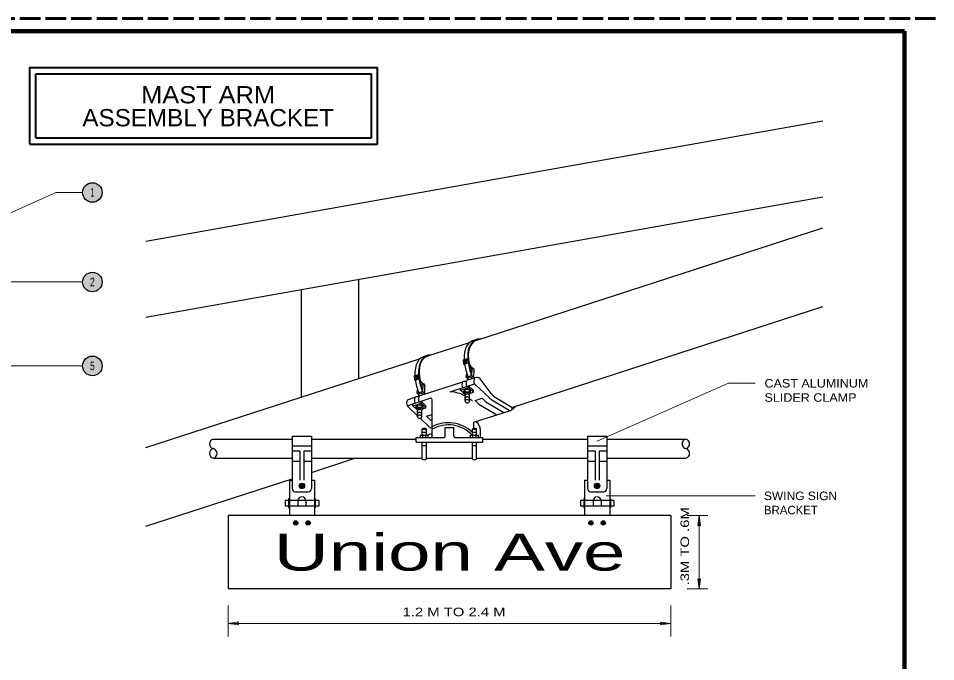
# Model space of a CAD drawing. Extents: x 312583 to 312853, y 144376 to 144586.
# Drawn here: x 312771.1 to 312851.8, y 144529.7 to 144586.2 of the extents above; entities that cross this region are included whole.
import ezdxf
from ezdxf.enums import TextEntityAlignment as Align

# ---------------------------------------------------------------- set-up
doc = ezdxf.new("R2010")
doc.units = 0
doc.header["$LTSCALE"] = 0.3
doc.linetypes.add('LONG_DASHED', pattern=[7.5, 6, -1.5])
for name, color, linetype, lineweight in [('1', 7, 'Continuous', 25), ('2', 7, 'Continuous', 13), ('63', 7, 'LONG_DASHED', 60)]:
    doc.layers.add(name, color=color, linetype=linetype, lineweight=lineweight)

msp = doc.modelspace()

# ---------------------------------------------------------------- hatches: boundary and pattern name
at = {"layer": '1'}
h = msp.add_hatch(color=256, dxfattribs=at)
edge = h.paths.add_edge_path()
edge.add_ellipse((312810.348, 144556.0743), major_axis=(-0.0325, -0.118), ratio=0.5966872, start_angle=0, end_angle=360)
h = msp.add_hatch(color=256, dxfattribs=at)
edge = h.paths.add_edge_path()
edge.add_ellipse((312806.0191, 144554.6706), major_axis=(-0.0325, -0.118), ratio=0.5966872, start_angle=0, end_angle=360)
for points in [[(312796.2425, 144545.1199, 1), (312795.7605, 144545.1199, 1)], [(312796.1712, 144545.1199, 1), (312795.8318, 144545.1199, 1)], [(312822.212, 144545.1199, 1), (312821.73, 144545.1199, 1)], [(312822.1407, 144545.1199, 1), (312821.8013, 144545.1199, 1)], [(312795.6532, 144541.8642, 1), (312795.2709, 144541.8642, 1)], [(312796.732, 144541.8642, 1), (312796.3497, 144541.8642, 1)], [(312821.6226, 144541.8642, 1), (312821.2403, 144541.8642, 1)], [(312822.7015, 144541.8642, 1), (312822.3192, 144541.8642, 1)]]:
    msp.add_hatch(color=256, dxfattribs=at).paths.add_polyline_path(points)
at = {"layer": '2'}
for points in [[(312778.4291, 144570.918, 1), (312776.7088, 144570.918, 1)], [(312778.4291, 144563.0427, 1), (312776.7088, 144563.0427, 1)], [(312778.4291, 144555.6707, 1), (312776.7088, 144555.6707, 1)]]:
    msp.add_hatch(color=256, dxfattribs=at).paths.add_polyline_path(points)

# ---------------------------------------------------------------- linework, layer by layer
at = {"layer": '1', "lineweight": 158}
msp.add_line((312849, 144423.1446), (312849, 144585.0846), dxfattribs=at)
at = {"layer": '1'}
for p, q in [((312782.2774, 144566.6365), (312841.8212, 144577.2025)), ((312782.2774, 144559.9598), (312841.8212, 144570.5258)), ((312811.3085, 144557.904), (312841.8212, 144567.8125)), ((312801.0203, 144554.5703), (312801.0203, 144563.2842)), ((312795.9641, 144552.9312), (312795.9641, 144562.386)), ((312814.4662, 144552.0144), (312841.8212, 144560.8951)), ((312807.0765, 144556.5427), (312810.7529, 144557.7373)), ((312782.2774, 144548.4955), (312806.4375, 144556.3297)), ((312810.2158, 144556.2001), (312810.5862, 144556.3205)), ((312810.688, 144556.2186), (312810.5862, 144556.3205)), ((312810.6325, 144555.9408), (312810.5862, 144556.3205)), ((312810.2528, 144555.8204), (312810.2158, 144556.2001)), ((312810.2528, 144555.8204), (312810.6325, 144555.9408)), ((312810.3269, 144555.7463), (312810.2528, 144555.8204)), ((312810.3176, 144555.9593), (312810.3917, 144555.9315)), ((312810.3824, 144556.1908), (312810.4473, 144556.1723)), ((312810.7343, 144555.8389), (312810.6325, 144555.9408)), ((312810.7343, 144555.8389), (312810.688, 144556.2186)), ((312810.6973, 144555.8297), (312810.7343, 144555.8389)), ((312805.8912, 144554.7925), (312806.2616, 144554.9129)), ((312805.9282, 144554.4129), (312805.8912, 144554.7925)), ((312806.0579, 144554.7925), (312806.1227, 144554.7647)), ((312806.2986, 144554.5332), (312806.2616, 144554.9129)), ((312806.3635, 144554.8203), (312806.2616, 144554.9129)), ((312806.4098, 144554.4314), (312806.3635, 144554.8203)), ((312810.4565, 144554.6814), (312810.5121, 144555.0055)), ((312810.4565, 144554.6814), (312810.9195, 144554.8296)), ((312810.4565, 144554.6814), (312810.6139, 144554.5055)), ((312810.7992, 144555.4037), (312811.0214, 144555.4778)), ((312810.9195, 144554.8296), (312811.0214, 144555.4778)), ((312810.9195, 144554.8296), (312811.1325, 144554.5888)), ((312811.1325, 144554.5888), (312811.1418, 144555.4037)), ((312805.9282, 144554.4129), (312806.2986, 144554.5332)), ((312805.993, 144554.348), (312805.9282, 144554.4129)), ((312805.993, 144554.5518), (312806.0579, 144554.5332)), ((312806.4098, 144554.4314), (312806.2986, 144554.5332)), ((312806.3264, 144553.0423), (312810.1602, 144554.2832)), ((312806.3727, 144554.4221), (312806.4098, 144554.4314)), ((312806.4746, 144553.9961), (312806.6968, 144554.0702)), ((312806.595, 144553.422), (312806.6968, 144554.0702)), ((312806.808, 144553.1905), (312806.808, 144553.9961)), ((312809.0397, 144553.3942), (312811.1881, 144554.0795)), ((312810.5213, 144554.4036), (312811.1973, 144554.6166)), ((312810.6139, 144554.4221), (312810.6139, 144554.5703)), ((312811.0955, 144553.5146), (312810.6695, 144553.9128)), ((312812.4938, 144552.8479), (312811.1881, 144554.0795)), ((312812.642, 144553.2461), (312811.6789, 144554.5332)), ((312806.132, 144553.2738), (312806.1783, 144553.5979)), ((312806.132, 144553.2738), (312806.595, 144553.422)), ((312806.132, 144553.2738), (312806.2801, 144553.0979)), ((312806.2801, 144552.9219), (312806.2801, 144553.1535)), ((312806.595, 144553.422), (312806.808, 144553.1905)), ((312810.3547, 144553.6165), (312810.2435, 144553.4683)), ((312810.3547, 144553.1812), (312810.2435, 144553.2553)), ((312810.3547, 144553.1535), (312810.2713, 144553.2368)), ((312810.3547, 144553.6165), (312810.7343, 144553.6165)), ((312810.3547, 144553.4035), (312810.3547, 144553.6165)), ((312810.3547, 144553.4035), (312810.7343, 144553.4035)), ((312810.3547, 144552.5608), (312810.3547, 144553.1812)), ((312811.0955, 144553.3572), (312810.6695, 144553.7646)), ((312810.7343, 144553.4035), (312810.7343, 144553.6165)), ((312810.7343, 144553.6165), (312810.8455, 144553.4683)), ((312810.7343, 144553.4035), (312810.8455, 144553.2553)), ((312810.8455, 144553.2553), (312810.7343, 144553.1812)), ((312810.7343, 144552.5608), (312810.7343, 144553.1812)), ((312810.8455, 144553.2553), (312810.8455, 144553.4683)), ((312805.2707, 144552.1626), (312805.7708, 144552.3293)), ((312805.2893, 144552.6997), (312805.9745, 144552.9219)), ((312805.7708, 144552.3293), (312806.4931, 144552.5701)), ((312805.7708, 144552.1719), (312805.7708, 144552.3293)), ((312806.4931, 144552.5701), (312807.2802, 144552.8201)), ((312806.9098, 144552.1533), (312806.4931, 144552.5701)), ((312806.9098, 144551.9959), (312806.4931, 144552.4034)), ((312807.4469, 144549.3845), (312807.4469, 144552.6997)), ((312811.5678, 144552.32), (312813.1513, 144551.3662)), ((312812.1789, 144552.5145), (312811.8548, 144552.8201)), ((312812.1789, 144552.5145), (312813.7717, 144551.5699)), ((312812.7068, 144552.6812), (312814.244, 144551.7644)), ((312812.9938, 144552.9127), (312814.4199, 144552.07)), ((312806.169, 144551.2921), (312805.3726, 144552.0422)), ((312806.0579, 144551.9033), (312805.7708, 144552.1719)), ((312806.169, 144552.2552), (312806.0579, 144552.1163)), ((312806.169, 144551.82), (312806.0579, 144551.9033)), ((312806.169, 144551.8014), (312806.0857, 144551.8848)), ((312806.169, 144552.2552), (312806.5487, 144552.2552)), ((312806.169, 144552.0422), (312806.169, 144552.2552)), ((312806.169, 144552.0422), (312806.5487, 144552.0422)), ((312806.169, 144551.1995), (312806.169, 144551.82)), ((312806.5487, 144552.0422), (312806.5487, 144552.2552)), ((312806.5487, 144552.2552), (312806.6598, 144552.1163)), ((312806.5487, 144552.0422), (312806.6598, 144551.9033)), ((312806.6598, 144551.9033), (312806.5487, 144551.82)), ((312806.5487, 144551.1995), (312806.5487, 144551.82)), ((312806.6598, 144551.9033), (312806.6598, 144552.1163)), ((312811.114, 144550.7087), (312814.3644, 144551.7551)), ((312807.1969, 144550.3105), (312806.4098, 144551.0606)), ((312806.9654, 144551.2366), (312807.4469, 144551.394)), ((312807.2895, 144550.931), (312806.9654, 144551.2366)), ((312807.2895, 144550.931), (312807.4469, 144550.8384)), ((312811.114, 144550.1716), (312811.114, 144550.7087)), ((312806.5857, 144549.579), (312806.5857, 144550.1346)), ((312806.9654, 144549.579), (312806.9654, 144550.1346)), ((312807.4099, 144550.2365), (312807.4469, 144550.2365)), ((312808.6045, 144550.2642), (312809.3545, 144550.2642)), ((312808.6045, 144549.4864), (312808.6045, 144550.2642)), ((312809.3545, 144549.4864), (312809.3545, 144550.2642)), ((312810.9936, 144549.579), (312810.9936, 144550.1346)), ((312811.3733, 144549.579), (312811.3733, 144550.1346)), ((312811.6974, 144549.3845), (312811.6974, 144550.0142)), ((312788.204, 144549.2363), (312795.1492, 144549.2363)), ((312795.1492, 144549.4864), (312795.1492, 144544.9025)), ((312795.1492, 144549.4864), (312796.8531, 144549.4864)), ((312796.8531, 144549.4864), (312796.8531, 144544.9025)), ((312796.8531, 144549.2363), (312806.0579, 144549.2363)), ((312806.0579, 144549.3845), (312808.5026, 144549.3845)), ((312806.0579, 144548.9585), (312806.0579, 144549.3845)), ((312806.4375, 144549.579), (312807.1135, 144549.579)), ((312806.4375, 144549.3845), (312806.4375, 144549.579)), ((312806.6413, 144549.3845), (312806.6413, 144549.579)), ((312806.9098, 144549.3845), (312806.9098, 144549.579)), ((312806.9561, 144549.579), (312807.4469, 144549.7364)), ((312807.1135, 144549.3845), (312807.1135, 144549.579)), ((312809.4564, 144549.3845), (312811.9104, 144549.3845)), ((312810.8455, 144549.579), (312811.5215, 144549.579)), ((312810.8455, 144549.3845), (312810.8455, 144549.579)), ((312811.0492, 144549.3845), (312811.0492, 144549.579)), ((312811.327, 144549.3845), (312811.327, 144549.579)), ((312811.5215, 144549.3845), (312811.5215, 144549.579)), ((312811.9104, 144548.9585), (312811.9104, 144549.3845)), ((312811.9104, 144549.2363), (312821.1151, 144549.2363)), ((312821.1151, 144549.4864), (312821.1151, 144544.9025)), ((312821.1151, 144549.4864), (312822.8283, 144549.4864)), ((312822.8283, 144549.4864), (312822.8283, 144544.9025)), ((312822.8283, 144549.2363), (312829.7735, 144549.2363)), ((312796.8531, 144548.6252), (312795.1492, 144548.6252)), ((312806.0579, 144548.9585), (312811.9104, 144548.9585)), ((312806.5857, 144547.4676), (312806.5857, 144548.9585)), ((312806.9654, 144547.4676), (312806.9654, 144548.9585)), ((312810.9936, 144547.4676), (312810.9936, 144548.9585)), ((312811.3733, 144547.4676), (312811.3733, 144548.9585)), ((312822.8283, 144548.6252), (312821.1151, 144548.6252)), ((312788.204, 144547.551), (312795.1492, 144547.551)), ((312795.8252, 144548.1621), (312795.1492, 144548.1621)), ((312795.8252, 144548.1621), (312795.8252, 144545.6156)), ((312796.1678, 144548.1621), (312796.1678, 144545.6156)), ((312796.8531, 144548.1621), (312796.1678, 144548.1621)), ((312796.8531, 144547.551), (312806.5857, 144547.551)), ((312796.8531, 144546.3101), (312800.6684, 144547.551)), ((312806.9654, 144547.551), (312810.9936, 144547.551)), ((312811.3733, 144547.551), (312821.1151, 144547.551)), ((312821.8004, 144548.1621), (312821.1151, 144548.1621)), ((312821.8004, 144548.1621), (312821.8004, 144545.6156)), ((312822.143, 144548.1621), (312822.143, 144545.6156)), ((312822.8283, 144548.1621), (312822.143, 144548.1621)), ((312822.8283, 144547.551), (312829.7735, 144547.551)), ((312795.1492, 144547.3009), (312795.8252, 144547.3009)), ((312796.1678, 144547.3009), (312796.8531, 144547.3009)), ((312821.1151, 144547.3009), (312821.8004, 144547.3009)), ((312822.143, 144547.3009), (312822.8283, 144547.3009)), ((312782.2774, 144541.5781), (312795.1492, 144545.7545)), ((312794.8992, 144545.6156), (312794.8992, 144542.5226)), ((312794.8992, 144545.6156), (312795.1492, 144545.6156)), ((312796.8531, 144545.6156), (312797.1031, 144545.6156)), ((312797.1031, 144545.6156), (312797.1031, 144542.5226)), ((312820.8651, 144545.6156), (312820.8651, 144542.5226)), ((312820.8651, 144545.6156), (312821.1151, 144545.6156)), ((312822.8283, 144545.6156), (312823.0783, 144545.6156)), ((312823.0783, 144545.6156), (312823.0783, 144542.5226)), ((312795.4455, 144544.5969), (312796.5568, 144544.5969)), ((312821.4115, 144544.5969), (312822.5227, 144544.5969)), ((312794.5195, 144543.8283), (312794.5195, 144543.3375)), ((312794.8251, 144543.8283), (312794.5195, 144543.8283)), ((312794.8251, 144543.9857), (312794.8251, 144543.1893)), ((312794.8992, 144543.9857), (312794.8251, 144543.9857)), ((312797.1031, 144543.8283), (312794.8992, 144543.8283)), ((312795.6493, 144543.8283), (312795.6493, 144543.3375)), ((312796.3531, 144543.8283), (312796.3531, 144543.3375)), ((312797.1772, 144543.9857), (312797.1031, 144543.9857)), ((312797.1772, 144543.9857), (312797.1772, 144543.1893)), ((312797.4828, 144543.8283), (312797.1772, 144543.8283)), ((312797.4828, 144543.8283), (312797.4828, 144543.3375)), ((312820.4947, 144543.8283), (312820.4947, 144543.3375)), ((312820.791, 144543.8283), (312820.4947, 144543.8283)), ((312820.791, 144543.9857), (312820.791, 144543.1893)), ((312820.8651, 144543.9857), (312820.791, 144543.9857)), ((312823.0783, 144543.8283), (312820.8651, 144543.8283)), ((312821.6152, 144543.8283), (312821.6152, 144543.3375)), ((312822.3283, 144543.8283), (312822.3283, 144543.3375)), ((312823.1524, 144543.9857), (312823.0783, 144543.9857)), ((312823.1524, 144543.9857), (312823.1524, 144543.1893)), ((312823.4487, 144543.8283), (312823.1524, 144543.8283)), ((312823.4487, 144543.8283), (312823.4487, 144543.3375)), ((312794.8251, 144543.3375), (312794.5195, 144543.3375)), ((312794.8992, 144543.1893), (312794.8251, 144543.1893)), ((312797.1031, 144543.3375), (312794.8992, 144543.3375)), ((312797.1772, 144543.1893), (312797.1031, 144543.1893)), ((312797.4828, 144543.3375), (312797.1772, 144543.3375)), ((312820.791, 144543.3375), (312820.4947, 144543.3375)), ((312820.8651, 144543.1893), (312820.791, 144543.1893)), ((312823.0783, 144543.3375), (312820.8651, 144543.3375)), ((312823.1524, 144543.1893), (312823.0783, 144543.1893)), ((312823.4487, 144543.3375), (312823.1524, 144543.3375)), ((312828.4401, 144542.5226), (312789.5282, 144542.5226)), ((312789.5282, 144542.5226), (312789.5282, 144536.0589)), ((312828.4401, 144542.5226), (312828.4401, 144536.0589)), ((312828.4401, 144536.0589), (312789.5282, 144536.0589))]:
    msp.add_line(p, q, dxfattribs=at)
at = {"layer": '1', "lineweight": 158}
msp.add_lwpolyline([(312616.5, 144423.1446), (312616.5, 144585.0846), (312849, 144585.0846)], dxfattribs=at)
at = {"layer": '1'}
for points in [[(312809.9657, 144553.5331), (312810.6695, 144553.7646), (312810.6695, 144553.9128)], [(312810.2435, 144553.2646), (312809.9657, 144553.5331), (312809.9657, 144553.6906)], [(312810.3547, 144553.4035), (312810.2435, 144553.2553), (312810.2435, 144553.4683)], [(312810.8455, 144553.2831), (312811.0955, 144553.3572), (312811.0955, 144553.5146)], [(312805.7708, 144552.1719), (312806.4931, 144552.4034), (312806.4931, 144552.5701)], [(312811.5678, 144552.32), (312811.2436, 144552.6256), (312811.8548, 144552.8201)], [(312806.169, 144552.0422), (312806.0579, 144551.9033), (312806.0579, 144552.1163)], [(312806.6598, 144551.9218), (312806.9098, 144551.9959), (312806.9098, 144552.1533)]]:
    msp.add_lwpolyline(points, dxfattribs=at)
at = {"layer": '1', "lineweight": 13}
for points in [[(312790.4265, 144532.9197), (312789.5282, 144533.0308), (312790.4265, 144533.1604), (312790.3431, 144533.0308)], [(312827.5418, 144533.1419), (312828.4401, 144533.0308), (312827.5418, 144532.9104), (312827.6252, 144533.0308)]]:
    msp.add_lwpolyline(points, close=True, dxfattribs=at)
at = {"layer": '1'}
for centre, radius in [((312796.0015, 144545.1199), 0.241), ((312796.0015, 144545.1199), 0.1697), ((312821.971, 144545.1199), 0.241), ((312821.971, 144545.1199), 0.1697), ((312795.462, 144541.8642), 0.1911), ((312796.5409, 144541.8642), 0.1911), ((312821.4315, 144541.8642), 0.1911), ((312822.5103, 144541.8642), 0.1911)]:
    msp.add_circle(centre, radius, dxfattribs=at)
for centre, radius, start, end in [((312811.5248, 144556.2842), 0.9407, 208.8117, 238.23982), ((312811.5248, 144556.2842), 0.9514, 210.65961, 238.36958), ((312810.7933, 144554.4975), 0.1934, 14.09154, 160.32275), ((312811.0054, 144555.3238), 0.1517, 329.08026, 82.28024), ((312811.0054, 144555.3238), 0.1624, 323.18665, 81.42866), ((312807.1954, 144554.8804), 0.9407, 208.8117, 238.23982), ((312807.1954, 144554.8804), 0.9514, 210.65961, 238.36958), ((312806.676, 144553.92), 0.1517, 329.08026, 82.28024), ((312806.676, 144553.92), 0.1624, 323.18665, 81.42866), ((312810.6121, 144554.0051), 0.529, 148.6862, 208.7998), ((312810.3054, 144553.9387), 0.3709, 64.61418, 113.03669), ((312810.9709, 144554.1215), 0.529, 148.6862, 208.7998), ((312811.6491, 144554.3414), 0.529, 148.6862, 208.7998), ((312811.3906, 144554.2928), 0.3769, 39.34483, 120.87266), ((312806.4638, 144553.0937), 0.1934, 14.09154, 160.32275), ((312808.8647, 144550.1937), 3.2015, 62.27071, 86.87926), ((312810.5419, 144553.1374), 0.1934, 14.09154, 165.90846), ((312810.5419, 144553.0123), 0.1934, 14.09154, 165.90846), ((312813.6402, 144553.993), 1.2508, 216.59815, 239.12378), ((312805.7381, 144552.4247), 0.529, 148.6862, 208.7998), ((312806.4258, 144552.6477), 0.529, 148.6862, 208.7998), ((312806.119, 144552.5813), 0.3709, 64.61418, 113.03669), ((312806.7845, 144552.764), 0.529, 148.6862, 208.7998), ((312807.3225, 144552.7024), 0.1251, 0, 107.96876), ((312810.5419, 144552.7621), 0.1934, 14.09154, 165.90846), ((312810.5419, 144552.512), 0.1934, 14.09154, 165.90846), ((312810.542, 144552.6061), 0.1934, 194.06, 345.87692), ((312808.8647, 144550.1937), 3.2015, 47.93634, 54.37324), ((312813.347, 144553.7596), 1.2508, 226.49505, 239.12699), ((312805.7151, 144552.4076), 0.5006, 208.34771, 226.92144), ((312806.3555, 144551.7799), 0.1934, 14.09154, 165.90846), ((312806.3555, 144551.6548), 0.1934, 14.09154, 165.90846), ((312806.3555, 144551.4047), 0.1934, 14.09154, 165.90846), ((312814.3105, 144551.9306), 0.1778, 248.42898, 49.82007), ((312806.3555, 144551.1545), 0.1934, 14.09154, 165.90846), ((312806.3556, 144551.2486), 0.1934, 194.06, 345.87692), ((312808.89, 144547.62), 3.0513, 46.29057, 118.21184), ((312810.8424, 144550.0355), 0.855, 358.52419, 58.42532), ((312806.778, 144549.7581), 0.4226, 63.64503, 116.35497), ((312806.778, 144550.5156), 0.4226, 243.64503, 296.35497), ((312806.778, 144550.2654), 0.4226, 243.64503, 296.35497), ((312807.4019, 144550.525), 0.2963, 226.12959, 272.25106), ((312808.89, 144547.62), 2.8636, 43.23977, 120.24547), ((312811.186, 144549.7581), 0.4226, 63.64503, 116.35497), ((312811.186, 144550.5156), 0.4226, 243.64503, 296.35497), ((312811.186, 144550.2654), 0.4226, 243.64503, 296.35497), ((312788.3035, 144548.815), 0.4329, 103.29315, 256.70685), ((312806.778, 144550.0152), 0.4226, 243.64503, 296.35497), ((312808.5092, 144549.4816), 0.1001, 270, 0), ((312809.4545, 144549.4816), 0.1001, 180, 270), ((312811.186, 144550.0152), 0.4226, 243.64503, 296.35497), ((312829.8731, 144548.815), 0.4329, 103.29315, 256.70685), ((312829.674, 144548.815), 0.4329, 283.29315, 76.70685), ((312788.3035, 144547.9723), 0.4329, 103.29315, 256.70685), ((312788.1044, 144547.9723), 0.4329, 283.29315, 76.70685), ((312806.778, 144549.0871), 0.4226, 243.64503, 296.35497), ((312811.186, 144549.0871), 0.4226, 243.64503, 296.35497), ((312829.674, 144547.9723), 0.4329, 283.29315, 76.70685), ((312806.778, 144547.8446), 0.4226, 243.64503, 296.35497), ((312811.186, 144547.8446), 0.4226, 243.64503, 296.35497), ((312795.4495, 144544.9018), 0.3002, 180, 270), ((312796.5534, 144544.9018), 0.3002, 270, 0), ((312821.419, 144544.9018), 0.3002, 180, 270), ((312822.5229, 144544.9018), 0.3002, 270, 0), ((312796.0015, 144543.8008), 0.3533, 5.25702, 174.74298), ((312821.971, 144543.8008), 0.3533, 5.25702, 174.74298)]:
    msp.add_arc(centre, radius, start, end, dxfattribs=at)
for centre, major_axis, ratio, start_param, end_param in [((312812.5405, 144554.7939), (-1.6434, 3.0309), 0.518166, 6.095077, 7.1120887), ((312812.8572, 144554.8966), (-1.6434, 3.0309), 0.518166, 5.9984099, 7.1120714), ((312812.8572, 144554.8966), (-1.6166, 2.9814), 0.51017, 6.1366037, 7.1267805), ((312812.5405, 144554.7939), (-1.6434, 3.0309), 0.518166, 5.998375, 6.0055532), ((312808.2119, 144553.3845), (-1.6434, 3.0309), 0.518166, 6.0952095, 7.1100407), ((312808.5286, 144553.4872), (-1.6434, 3.0309), 0.518166, 6.0072786, 7.1100401), ((312808.5286, 144553.4872), (-1.6166, 2.9814), 0.51017, 6.1789794, 7.1246878), ((312812.5405, 144554.7939), (-1.6434, 3.0309), 0.518166, 0.9598531, 1.3177127), ((312810.4173, 144556.0529), (-0.0325, -0.118), 0.596687, 0.0000566, 3.1416656), ((312812.8572, 144554.8966), (-1.6434, 3.0309), 0.518166, 0.9601001, 1.3176965), ((312812.8572, 144554.8966), (-1.6166, 2.9814), 0.51017, 0.9789458, 1.2850851), ((312806.0884, 144554.6493), (-0.0325, -0.118), 0.596687, 0.0000566, 3.1416656), ((312808.2119, 144553.3845), (-1.6434, 3.0309), 0.518166, 0.9579706, 1.3160528), ((312808.5286, 144553.4872), (-1.6434, 3.0309), 0.518166, 0.957976, 1.3160501), ((312808.5286, 144553.4872), (-1.6166, 2.9814), 0.51017, 0.97675, 1.2840271), ((312812.8572, 144554.8966), (-1.6434, 3.0309), 0.518166, 3.1212356, 3.363281), ((312812.8572, 144554.8966), (-1.6166, 2.9814), 0.51017, 3.1508955, 3.309058)]:
    msp.add_ellipse(centre, major_axis=major_axis, ratio=ratio, start_param=start_param, end_param=end_param, dxfattribs=at)
for centre in [(312810.348, 144556.0743), (312806.0191, 144554.6706)]:
    msp.add_ellipse(centre, major_axis=(-0.0325, -0.118), ratio=0.596687, dxfattribs=at)
at = {"layer": '2', "lineweight": 40}
for p, q in [((312772.5963, 144575.7146), (312772.5963, 144581.3541)), ((312772.5963, 144581.3541), (312802.1182, 144581.3541)), ((312802.1182, 144575.7146), (312802.1182, 144581.3541)), ((312802.6553, 144575.1775), (312802.6553, 144581.9005)), ((312772.5963, 144575.7146), (312802.1182, 144575.7146)), ((312772.0592, 144575.1775), (312802.6553, 144575.1775))]:
    msp.add_line(p, q, dxfattribs=at)
at = {"layer": '2'}
for p, q in [((312756.6037, 144562.9261), (312774.3557, 144570.9177)), ((312774.3557, 144570.9177), (312776.7079, 144570.9177)), ((312762.5488, 144563.0465), (312776.7079, 144563.0465)), ((312762.5488, 144555.6753), (312776.7079, 144555.6753)), ((312821.9856, 144549.0604), (312833.5147, 144554.1443)), ((312833.5147, 144554.1443), (312835.8668, 144554.1443)), ((312822.7635, 144544.2358), (312835.8668, 144544.2358)), ((312831.7138, 144542.5226), (312829.8847, 144542.5226)), ((312830.9422, 144536.0589), (312830.9422, 144542.5226)), ((312831.7138, 144536.0589), (312829.8847, 144536.0589)), ((312789.5282, 144531.8825), (312789.5282, 144534.6143)), ((312828.4401, 144531.8825), (312828.4401, 144534.6143)), ((312789.5282, 144533.0308), (312828.4401, 144533.0308))]:
    msp.add_line(p, q, dxfattribs=at)
at = {"layer": '2', "lineweight": 40}
msp.add_lwpolyline([(312772.0592, 144575.1775), (312772.0592, 144581.9005), (312802.6553, 144581.9005)], dxfattribs=at)
at = {"layer": '2'}
for points in [[(312830.8311, 144541.6151), (312830.9422, 144542.5226), (312831.0626, 144541.6151), (312830.9422, 144541.6984)], [(312831.0626, 144536.9572), (312830.9422, 144536.0589), (312830.8311, 144536.9572), (312830.9422, 144536.8646)]]:
    msp.add_lwpolyline(points, close=True, dxfattribs=at)
at = {"layer": '2', "lineweight": 25}
for centre in [(312777.5689, 144570.918), (312777.5689, 144563.0427), (312777.5689, 144555.6707)]:
    msp.add_circle(centre, 0.8601, dxfattribs=at)
at = {"layer": '63'}
msp.add_line((312851.75, 144586.2246), (312583.526, 144586.2246), dxfattribs=at)

# ---------------------------------------------------------------- texts
at = {"layer": '1', "width": 1.55}
msp.add_text('Union Ave', height=3.236, dxfattribs=at).set_placement((312808.9888, 144537.6702), align=Align.CENTER)
at = {"layer": '2'}
for s, height, width, p in [('MAST ARM', 1.517, 1.1, (312787.7507, 144578.752)), ('ASSEMBLY BRACKET', 1.517, 1.05, (312787.7554, 144576.7332)), ('1', 0.7505, 0.5, (312777.5645, 144570.5473)), ('2', 0.7505, 0.75, (312777.569, 144562.6668)), ('5', 0.7505, 0.75, (312777.569, 144555.2956))]:
    msp.add_text(s, height=height, dxfattribs=dict(at, width=width)).set_placement(p, align=Align.CENTER)
for s, height, width, p in [('CAST ALUMINUM', 0.7505, 1.1, (312836.691, 144553.7646)), ('SLIDER CLAMP', 0.7505, 1.1, (312836.691, 144552.5145)), ('SWING SIGN', 0.7501, 1.05, (312836.6447, 144543.8711)), ('1.2 M TO 2.4 M', 0.7501, 1.3, (312804.8552, 144533.6658))]:
    msp.add_text(s, height=height, dxfattribs=dict(at, width=width)).set_placement(p)
msp.add_text('BRACKET', height=0.7501, dxfattribs=at).set_placement((312836.6447, 144542.621))
at = {"layer": '2', "width": 1.3}
msp.add_text('.3M TO .6M', height=0.7501, rotation=90, dxfattribs=at).set_placement((312830.0568, 144536.3647))

doc.saveas('drawing.dxf')
